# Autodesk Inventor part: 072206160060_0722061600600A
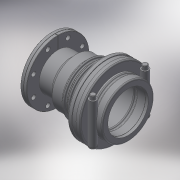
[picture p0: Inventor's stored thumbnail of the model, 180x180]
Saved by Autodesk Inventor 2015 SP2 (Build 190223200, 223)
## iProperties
Created: 2017-05
Part Number: 072206160060_0722061600600A
Material: Generic
Description: PLASSON COMPRESSION FLANGE ADAPTOR 160-6"
Document SubType Name: Modeling
Designer: KIM
Density: 1 g/cm^3
Appearance: Default
Author: KIM
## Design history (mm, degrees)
derived "072206.ipt"
feature "Solid1::072206.ipt"
tag "TaggingFeature1"
body "Solid1"
other parameters: "d0" = 304, "d3" = 208, "d4" = 192, "d5" = 4.8, "d6" = 51, "d7" = 274.4, "d9" = 204, "d10" = 51, "d11" = 9.6, "d12" = 51, "d13" = 10.2, "d15" = 4.8, "d17" = 161.6, "d18" = 11.55, "d19" = 0, "d21" = 0, "d23" = 20.16, "d24" = 16, "d25" = 0, "d26" = 1.6, "d29" = 0.1, "d30" = 8, "d31" = 0, "d32" = 4.8, "d40" = 285, "d41" = 135 deg, "d42" = 24.32, "d43" = 1, "d44" = 1, "d45" = 171, "d46" = 76, "d47" = 22, "d50" = 0, "d52" = 360 deg, "d60" = 22.5 deg, "d61" = 2, "d62" = 1, "d63" = 12.16, "d64" = 0, "d66" = 360 deg, "d68" = 1.425, "d71" = 1, "d72" = 1, "d75" = 360 deg, "l_" = 204, "H_" = 304, "D_" = 285, "S_" = 22, "d16" = 46.2, "d22" = 28.8
